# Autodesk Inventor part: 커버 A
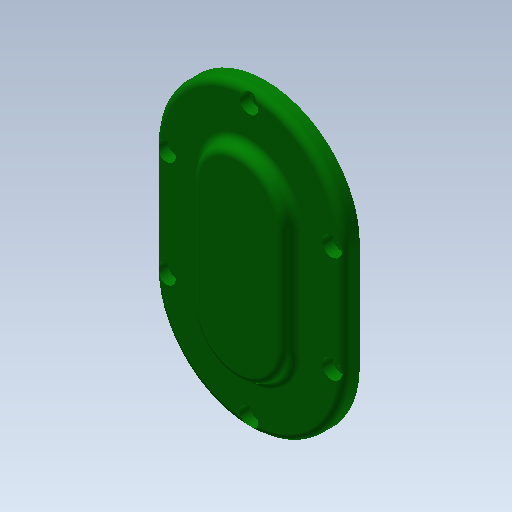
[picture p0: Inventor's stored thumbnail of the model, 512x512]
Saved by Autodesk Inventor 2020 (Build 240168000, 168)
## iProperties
Created: 2020-04
Part Number: 커버 A
Material: 알루미늄 6061
Document SubType Name: Modeling
Designer: mduedu
Density: 2.71 g/cm^3
Mass: 189.426 g
Surface Area: 209.668 cm^2
Volume: 69.8987 cm^3
Appearance: 진녹색
Author: mduedu
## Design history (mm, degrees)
sketch "스케치1"
  geometry: L1 (-40, 0)-(-40, -45); L2 (40, 0)-(40, -45); A1 r 40 centre (0, 0) between (40, 0) and (-40, 0); A2 r 40 centre (0, -45) between (-40, -45) and (40, -45); 1 further point
  constraints: 4 end point, 4 point on circle, 4 tangent, 2 centre point, 1 coincident, 1 equal radius, 1 vertical alignment
  dimensions: "d0" = 80 diameter of A1; "d31" = 45 distance of point (0, 0) A2.centre
extrude "돌출1" new body sketch "스케치1" distance "d1" = 7; taper "d2" = 0 deg
fillet "모깎기2" dims "d7" = 3
sketch "스케치4"
  geometry: L1 (30, 0)-(30, -45); L2 (-30, 0)-(-30, -45); A1 r 30 centre (0, 0) between (30, 0) and (-30, 0); A2 r 30 centre (0, -45) between (-30, -45) and (30, -45); 1 further point
  constraints: 4 end point, 4 point on circle, 4 tangent, 2 centre point, 1 coincident, 1 equal radius, 1 vertical alignment
  dimensions: "d19" = 60 diameter of A1; "d38" = 45 distance of point (0, 0) A2.centre
extrude "돌출3" join sketch "스케치4" distance "d20" = 4; taper "d21" = 0 deg
sketch "스케치7"
  geometry: L1 (-20, 0)-(-20, -45); L2 (20, 0)-(20, -45); A1 r 20 centre (0, 0) between (20, 0) and (-20, 0); A2 r 20 centre (0, -45) between (-20, -45) and (20, -45); 1 further point
  constraints: 4 end point, 4 point on circle, 4 tangent, 2 centre point, 1 coincident, 1 equal radius, 1 vertical alignment
  dimensions: "d45" = 40 diameter of A1; "d47" = 45 distance of point (0, 0) A2.centre
extrude "돌출5" join sketch "스케치7" distance "d48" = 5; taper "d49" = -15 deg
fillet "모깎기4" dims "d50" = 3
chamfer "모따기2" distance "d58" = 1; stored, may be unused: second distance "d59" = 2, angle "d60" = 45 deg
sketch "스케치6"
  geometry: L1 (0, 7)-(37, 7) reference; L2 (0, -4)-(30, -4) reference; L3 (0, -4)-(0, 8); L4 (0, 8)-(8, 8); L5 (11, 5)-(11, 5); L6 (11, 5)-(16, 5); L7 (16, 5)-(16, -4); L8 (-45, -4)-(-45, 8); L9 (-45, 8)-(-37, 8); L10 (-34, 5)-(-34, 4); L11 (-34, 4)-(-31, 4); L12 (-31, 4)-(-31, -4); L13 (-31, -4)-(-45, -4); A1 r 3 centre (8, 5) between (11, 5) and (8, 8); A2 r 3 centre (-37, 5) between (-34, 5) and (-37, 8); 3 further points
  constraints: 22 end point, 5 parallel, 5 point on line, 4 perpendicular, 4 point on circle, 4 tangent, 2 centre point, 2 horizontal alignment, 1 horizontal, 1 vertical
  dimensions: "d39" = 32 diameter of L7 L3; "d41" = 3 distance of point (11, 8) L5.end; "d42" = 9 distance of L6.end L7.end; "d43" = 22 diameter of L5 L3; "d44" = 3 radius of A1; "d51" = 8 distance of L11.end L12.end; "d52" = 45 distance of L2.start L8.start; "d53" = 28 diameter of L12 L8; "d54" = 22 diameter of L10 L8; "d55" = 3 radius of A2
revolve "회전1" stored, may be unused: angle "d56" = 90 deg
revolve "회전2" stored, may be unused: angle "d57" = 90 deg
sketch "스케치3"
  geometry: A1 r 35 centre (0, 0) between (0, 35) and (-35, 0); A2 r 35 centre (0, -45) between (-35, -45) and (0, -80); 3 further points
  constraints: 6 point on circle, 5 vertical alignment, 2 centre point, 2 horizontal alignment, 1 coincident, 1 equal radius
  dimensions: "d8" = 70 diameter of A1; "d69" = 45 distance of point (0, 0) A2.centre
hole "구멍1" sketch "스케치3" at (0, 35), (-35, 0), (-35, -45), (0, -80), (35, -45), (35, 0) diameter "d9" = 4.5; stored, may be unused: countersink angle "d13" = 90 deg, drill point angle "d15" = 118 deg; dims "d10" = 6, "d11" = 8, "d12" = 4.4, "d14" = 8
fillet "모깎기5" dims "d70" = 0.3
chamfer "모따기3" distance "d71" = 1; stored, may be unused: second distance "d72" = 2, angle "d73" = 45 deg
node "솔리드1"
